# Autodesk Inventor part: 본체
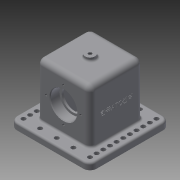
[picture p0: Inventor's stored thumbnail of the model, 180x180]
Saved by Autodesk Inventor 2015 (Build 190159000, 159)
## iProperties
Created: 2018-11
Part Number: 본체
Material: 일반
Document SubType Name: Modeling
Designer: now
Density: 1 g/cm^3
Appearance: 기본값
Author: now
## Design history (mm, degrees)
sketch "스케치1"
  geometry: L1 (-60, 60)-(60, 60); L2 (60, 60)-(60, -60); L3 (60, -60)-(-60, -60); L4 (-60, -60)-(-60, 60); L5 (-60, 60)-(60, -60); L6 (60, 60)-(-60, -60); 1 further point
  constraints: 12 end point, 2 midpoint, 2 parallel, 1 horizontal, 1 perpendicular
  dimensions: "d0" = 120 distance of L2.end L3.end; "d1" = 120 distance of L1.end L2.end
extrude "돌출1" new body sketch "스케치1" distance "d2" = 10; taper "d3" = 0 deg
sketch "스케치2"
  geometry: L1 (-40, 40)-(40, 40); L2 (40, 40)-(40, -40); L3 (40, -40)-(-40, -40); L4 (-40, -40)-(-40, 40); L5 (-40, 40)-(40, -40); L6 (40, 40)-(-40, -40); 1 further point
  constraints: 12 end point, 2 midpoint, 2 parallel, 1 horizontal, 1 perpendicular
  dimensions: "d4" = 80 distance of L2.end L3.end; "d5" = 80 distance of L1.end L2.end
extrude "돌출2" join sketch "스케치2" distance "d6" = 80; taper "d7" = 0 deg
sketch "스케치3"
  geometry: L1 (30, 23)-(-30, 23); L2 (-30, 23)-(-30, -23); L3 (-30, -23)-(30, -23); L4 (30, -23)-(30, 23); L5 (30, 23)-(-30, -23); L6 (-30, 23)-(30, -23); 1 further point
  constraints: 12 end point, 2 midpoint, 2 parallel, 1 horizontal, 1 perpendicular
  dimensions: "d8" = 46 distance of L3.end L1.start; "d9" = 60 distance of L2.end L3.end
extrude "돌출3" cut sketch "스케치3" distance "d10" = 80; taper "d11" = 0 deg
sketch "스케치4"
  geometry: L1 (100, -10)-(-20, -10) reference; C1 r 16.5 at (40, 38); 2 further points
  constraints: 1 centre point, 1 midpoint, 1 vertical alignment
  dimensions: "d12" = 33 diameter of C1; "d13" = 48 distance from line of L1 C1.centre
extrude "돌출4" cut sketch "스케치4" stored distance "d14" = 80; taper "d15" = 0 deg
sketch "스케치5"
  geometry: C1 r 16.5 at (40, 38) reference; C2 r 20 at (40, 38); 1 further point
  constraints: 1 centre point, 1 coincident
  dimensions: "d16" = 40 diameter of C2
extrude "돌출5" cut sketch "스케치5" distance "d17" = 14; taper "d18" = 0 deg
sketch "스케치6"
  geometry: C1 r 20 at (40, 38) reference; 2 further points
  constraints: 1 vertical alignment
  dimensions: "d19" = 26 distance of C1.centre point (40, 64)
hole "구멍1" sketch "스케치6" at (40, 64) diameter "d20" = 3.242; stored, may be unused: countersink angle "d24" = 90 deg, drill point angle "d26" = 118 deg; dims "d21" = 8, "d22" = 4, "d23" = 2, "d25" = 10
fillet "모깎기1" dims "d30" = 10
sketch "스케치7"
  geometry: C1 r 7.5 at (0, 0); 1 further point
  constraints: 1 centre point, 1 coincident
  dimensions: "d31" = 15 diameter of C1
extrude "돌출6" join sketch "스케치7" distance "d32" = 5; taper "d33" = 0 deg
sketch "스케치8"
  geometry: C1 r 7.5 at (0, 0) reference
hole "구멍2" sketch "스케치8" at (0, 0) diameter "d34" = 4.917; stored, may be unused: countersink angle "d38" = 90 deg, drill point angle "d40" = 118 deg; dims "d35" = 12, "d36" = 4, "d37" = 2, "d39" = 17.1
sketch "스케치9"
  geometry: L1 (10, 90)-(10, -10) reference; 3 further points
  constraints: 1 horizontal alignment, 1 midpoint, 1 other
  dimensions: "d41" = 48 distance from line of L1 point (-38, 40)
sketch "스케치10"
  geometry: A1 r 10 centre (-50, -50) between (-60, -50) and (-50, -60) reference; 1 further point
hole "구멍3" sketch "스케치10" at (-50, -50) diameter "d42" = 6.6; stored, may be unused: countersink angle "d46" = 90 deg, drill point angle "d48" = 118 deg; dims "d43" = 12, "d44" = 4, "d45" = 2, "d47" = 17.1
feature "엠보싱1" dims "d0" = 120, "d1" = 120, "d8" = 46, "d9" = 60, "d61" = 0.5, "d62" = 0
fillet "모깎기2" dims "d63" = 8
fillet "모깎기3" dims "d64" = 8
fillet "모깎기4" dims "d65" = 3
fillet "모깎기5" dims "d66" = 3
fillet "모깎기6" dims "d67" = 3
chamfer "모따기1" distance "d68" = 1; stored, may be unused: second distance "d69" = 2, angle "d70" = 45 deg
node "솔리드1"
pattern_circular "원형 패턴1" dims angle "d28" = 360 deg
mirror "대칭1"
pattern_linear "직사각형 패턴1" dims "d51" = 10
pattern_linear "직사각형 패턴2" dims "d57" = 25
